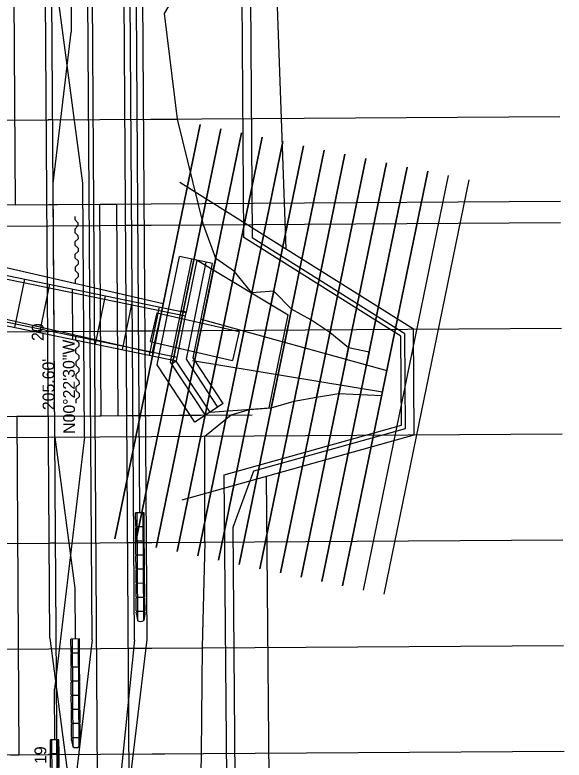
# Model space of a CAD drawing. Extents: x 2283072 to 2287933, y 586198 to 587702.
# Drawn here: x 2284424.4 to 2284554.3, y 587086.3 to 587262.4 of the extents above; entities that cross this region are included whole.
import ezdxf

# ---------------------------------------------------------------- set-up
doc = ezdxf.new("R2010")
doc.units = 0
for name, color, linetype in [('_CIVIL_CONSTRUCTION', 7, 'Continuous'), ('DR_X_Ditch', 7, 'Continuous'), ('DR_X_Headwall', 7, 'Continuous'), ('DT_X_Contour_Major', 7, 'Continuous'), ('DT_X_Island', 7, 'Continuous'), ('DT_X_Terrain_Boundary', 7, 'Continuous'), ('DT_X_Void', 7, 'Continuous'), ('HY_X_Water_Edge', 7, 'Continuous'), ('PV_X_Driveway', 7, 'Continuous'), ('PV_X_Shoulder_Aggregate', 7, 'Continuous'), ('RD_P_Fence', 7, 'Continuous'), ('RD_X_Cells', 7, 'Continuous'), ('RD_X_Fence', 7, 'Continuous'), ('RD_X_Gate', 7, 'Continuous'), ('RS_Raster1', 7, 'Continuous'), ('RW_P_Esmt_SH', 7, 'Continuous'), ('RW_P_Esmt_TMP', 7, 'Continuous'), ('SV_P_Control_Cells_Set', 7, 'Continuous'), ('SV_P_Mon_Cells_Set', 7, 'Continuous'), ('SV_X_Control_Cells_Found', 7, 'Continuous'), ('SV_X_Random_Point', 7, 'Continuous'), ('SV_X_Toe_of_Slope', 7, 'Continuous')]:
    doc.layers.add(name, color=color, linetype=linetype)

msp = doc.modelspace()

# ---------------------------------------------------------------- linework, layer by layer
at = {"layer": '_CIVIL_CONSTRUCTION'}
for p, q in [((2284440.46, 587222.64), (2284432.57, 587282.12)), ((2284442.67, 587114.69), (2284441.59, 587278.56)), ((2284452.67, 587114.75), (2284451.59, 587278.62)), ((2284453.97, 587144.73), (2284453.18, 587264.73)), ((2284440.85, 587162.64), (2284440.46, 587222.64)), ((2284440.85, 587162.64), (2284433.74, 587103.07)), ((2284454.97, 587144.74), (2284452.97, 587144.72)), ((2284452.99, 587141.56), (2284452.97, 587144.72)), ((2284453.47, 587119.24), (2284453.3, 587144.72)), ((2284454.64, 587144.73), (2284454.8, 587119.25)), ((2284454.99, 587141.57), (2284454.97, 587144.74)), ((2284452.99, 587141.56), (2284453.16, 587141.39)), ((2284453.16, 587141.39), (2284452.99, 587141.22)), ((2284453.01, 587138.22), (2284452.99, 587141.22)), ((2284454.83, 587141.4), (2284453.16, 587141.39)), ((2284454.99, 587141.57), (2284454.83, 587141.4)), ((2284454.83, 587141.4), (2284454.99, 587141.24)), ((2284455.01, 587138.24), (2284454.99, 587141.24)), ((2284453.01, 587138.22), (2284453.18, 587138.06)), ((2284455.01, 587138.24), (2284454.85, 587138.07)), ((2284453.18, 587138.06), (2284453.02, 587137.89)), ((2284453.03, 587134.89), (2284453.02, 587137.89)), ((2284454.85, 587138.07), (2284453.18, 587138.06)), ((2284454.85, 587138.07), (2284455.02, 587137.9)), ((2284455.03, 587134.9), (2284455.02, 587137.9)), ((2284453.03, 587134.89), (2284453.2, 587134.72)), ((2284453.2, 587134.72), (2284453.04, 587134.56)), ((2284454.87, 587134.73), (2284453.2, 587134.72)), ((2284455.03, 587134.9), (2284454.87, 587134.73)), ((2284454.87, 587134.73), (2284455.04, 587134.57)), ((2284453.06, 587131.56), (2284453.04, 587134.56)), ((2284455.06, 587131.57), (2284455.04, 587134.57)), ((2284453.06, 587131.56), (2284453.22, 587131.39)), ((2284453.22, 587131.39), (2284453.06, 587131.22)), ((2284453.08, 587128.22), (2284453.06, 587131.22)), ((2284454.89, 587131.4), (2284453.22, 587131.39)), ((2284455.06, 587131.57), (2284454.89, 587131.4)), ((2284454.89, 587131.4), (2284455.06, 587131.24)), ((2284455.08, 587128.24), (2284455.06, 587131.24)), ((2284453.08, 587128.22), (2284453.25, 587128.06)), ((2284453.25, 587128.06), (2284453.08, 587127.89)), ((2284453.1, 587124.89), (2284453.08, 587127.89)), ((2284454.91, 587128.07), (2284453.25, 587128.06)), ((2284455.08, 587128.24), (2284454.91, 587128.07)), ((2284454.91, 587128.07), (2284455.08, 587127.9)), ((2284455.08, 587127.9), (2284455.1, 587124.9)), ((2284453.1, 587124.89), (2284453.27, 587124.72)), ((2284453.27, 587124.72), (2284453.1, 587124.56)), ((2284453.12, 587121.56), (2284453.1, 587124.56)), ((2284454.93, 587124.74), (2284453.27, 587124.72)), ((2284455.1, 587124.9), (2284454.93, 587124.74)), ((2284454.93, 587124.74), (2284455.1, 587124.57)), ((2284455.1, 587124.57), (2284455.12, 587121.57)), ((2284453.12, 587121.56), (2284453.29, 587121.39)), ((2284453.29, 587121.39), (2284453.12, 587121.22)), ((2284453.13, 587120.79), (2284453.12, 587121.22)), ((2284453.13, 587120.79), (2284453.39, 587119.29)), ((2284454.96, 587121.4), (2284453.29, 587121.39)), ((2284455.13, 587120.8), (2284454.89, 587119.3)), ((2284455.12, 587121.57), (2284454.96, 587121.4)), ((2284454.96, 587121.4), (2284455.12, 587121.24)), ((2284455.12, 587121.24), (2284455.13, 587120.8)), ((2284442.67, 587114.69), (2284426.32, 586977.76)), ((2284452.67, 587114.75), (2284444.91, 587037.77)), ((2284433.82, 587091.07), (2284433.74, 587103.07)), ((2284434.82, 587091.07), (2284432.82, 587091.06)), ((2284432.84, 587087.89), (2284432.82, 587091.06)), ((2284433.32, 587065.57), (2284433.15, 587091.06)), ((2284434.49, 587091.07), (2284434.65, 587065.58)), ((2284434.84, 587087.91), (2284434.82, 587091.07)), ((2284432.84, 587087.89), (2284433.01, 587087.73)), ((2284433.01, 587087.73), (2284432.84, 587087.56)), ((2284432.86, 587084.56), (2284432.84, 587087.56)), ((2284434.68, 587087.74), (2284433.01, 587087.73)), ((2284434.84, 587087.91), (2284434.68, 587087.74)), ((2284434.68, 587087.74), (2284434.84, 587087.57)), ((2284434.86, 587084.57), (2284434.84, 587087.57))]:
    msp.add_line(p, q, dxfattribs=at)
msp.add_arc((2284454.13, 587120.4), 1.34, 236.1994, 304.5508, dxfattribs=at)
at = {"layer": 'DR_X_Ditch'}
for p, q in [((2284432.66, 587115.11), (2284431.63, 587272.79)), ((2284437.65, 587270.34), (2284437.73, 587258.34)), ((2284433.46, 587222.6), (2284437.73, 587258.34)), ((2284433.85, 587162.6), (2284433.46, 587222.6)), ((2284433.85, 587162.6), (2284438.59, 587126.91)), ((2284438.59, 587126.91), (2284438.67, 587114.91)), ((2284432.66, 587115.11), (2284445.17, 587020.81)), ((2284439.67, 587114.92), (2284437.67, 587114.9)), ((2284437.69, 587111.74), (2284437.67, 587114.9)), ((2284438.17, 587089.42), (2284438, 587114.91)), ((2284439.33, 587114.91), (2284439.5, 587089.43)), ((2284439.69, 587111.75), (2284439.67, 587114.92)), ((2284437.69, 587111.74), (2284437.85, 587111.57)), ((2284437.85, 587111.57), (2284437.69, 587111.4)), ((2284437.71, 587108.4), (2284437.69, 587111.4)), ((2284439.52, 587111.58), (2284437.85, 587111.57)), ((2284439.69, 587111.75), (2284439.52, 587111.58)), ((2284439.52, 587111.58), (2284439.69, 587111.42)), ((2284439.71, 587108.42), (2284439.69, 587111.42)), ((2284437.71, 587108.4), (2284437.88, 587108.24)), ((2284439.71, 587108.42), (2284439.54, 587108.25)), ((2284437.88, 587108.24), (2284437.71, 587108.07)), ((2284437.73, 587105.07), (2284437.71, 587108.07)), ((2284439.54, 587108.25), (2284437.88, 587108.24)), ((2284439.54, 587108.25), (2284439.71, 587108.08)), ((2284439.73, 587105.08), (2284439.71, 587108.08)), ((2284437.73, 587105.07), (2284437.9, 587104.91)), ((2284437.9, 587104.91), (2284437.73, 587104.74)), ((2284439.56, 587104.92), (2284437.9, 587104.91)), ((2284439.73, 587105.08), (2284439.56, 587104.92)), ((2284439.56, 587104.92), (2284439.73, 587104.75)), ((2284439.75, 587101.75), (2284439.73, 587104.75)), ((2284437.75, 587101.74), (2284437.73, 587104.74)), ((2284437.75, 587101.74), (2284437.92, 587101.57)), ((2284437.92, 587101.57), (2284437.75, 587101.4)), ((2284437.77, 587098.4), (2284437.75, 587101.4)), ((2284439.59, 587101.58), (2284437.92, 587101.57)), ((2284439.75, 587101.75), (2284439.59, 587101.58)), ((2284439.59, 587101.58), (2284439.75, 587101.42)), ((2284439.77, 587098.42), (2284439.75, 587101.42)), ((2284437.77, 587098.4), (2284437.94, 587098.24)), ((2284437.94, 587098.24), (2284437.78, 587098.07)), ((2284437.8, 587095.07), (2284437.78, 587098.07)), ((2284439.61, 587098.25), (2284437.94, 587098.24)), ((2284439.77, 587098.42), (2284439.61, 587098.25)), ((2284439.61, 587098.25), (2284439.78, 587098.08)), ((2284439.78, 587098.08), (2284439.8, 587095.08)), ((2284437.8, 587095.07), (2284437.96, 587094.91)), ((2284437.96, 587094.91), (2284437.8, 587094.74)), ((2284437.82, 587091.74), (2284437.8, 587094.74)), ((2284439.63, 587094.92), (2284437.96, 587094.91)), ((2284439.8, 587095.08), (2284439.63, 587094.92)), ((2284439.63, 587094.92), (2284439.8, 587094.75)), ((2284439.8, 587094.75), (2284439.82, 587091.75)), ((2284437.82, 587091.74), (2284437.98, 587091.57)), ((2284437.98, 587091.57), (2284437.82, 587091.4)), ((2284437.82, 587090.97), (2284437.82, 587091.4)), ((2284437.82, 587090.97), (2284438.08, 587089.47)), ((2284439.65, 587091.58), (2284437.98, 587091.57)), ((2284439.82, 587090.98), (2284439.58, 587089.48)), ((2284439.82, 587091.75), (2284439.65, 587091.58)), ((2284439.65, 587091.58), (2284439.82, 587091.42)), ((2284439.82, 587091.42), (2284439.82, 587090.98))]:
    msp.add_line(p, q, dxfattribs=at)
msp.add_arc((2284438.82, 587090.58), 1.34, 236.1994, 304.5508, dxfattribs=at)
at = {"layer": 'DR_X_Headwall'}
for p, q in [((2284480.09, 587278.8), (2284480.55, 587209.72)), ((2284516.69, 587187.04), (2284480.55, 587209.72)), ((2284516.84, 587164.67), (2284516.69, 587187.04)), ((2284480.95, 587154.63), (2284516.84, 587164.67)), ((2284476.02, 587141.37), (2284480.95, 587154.63)), ((2284476.87, 587042.07), (2284476.02, 587141.37))]:
    msp.add_line(p, q, dxfattribs=at)
at = {"layer": 'DT_X_Contour_Major'}
for p, q in [((2284458.07, 587179.74), (2284463.32, 587205.3)), ((2284471.16, 587203.68), (2284463.32, 587205.3)), ((2284403.08, 587203.99), (2284464.78, 587191.3)), ((2284403.24, 587204.81), (2284464.95, 587192.11)), ((2284463.74, 587192.45), (2284466.26, 587204.69)), ((2284464.97, 587192.2), (2284467.49, 587204.44)), ((2284464.98, 587181.07), (2284469.69, 587203.99)), ((2284466.57, 587181.37), (2284471.16, 587203.68)), ((2284424.4, 587188.55), (2284426.75, 587199.97)), ((2284430.28, 587187.34), (2284432.63, 587198.76)), ((2284438.11, 587185.72), (2284438.02, 587197.66)), ((2284443.5, 587184.62), (2284445.85, 587196.04)), ((2284449.87, 587183.31), (2284452.22, 587194.73)), ((2284400.89, 587193.38), (2284462.6, 587180.69)), ((2284401.06, 587194.2), (2284462.77, 587181.5)), ((2284456.23, 587182), (2284458.58, 587193.42)), ((2284461.25, 587180.35), (2284463.74, 587192.45)), ((2284462.6, 587180.69), (2284464.95, 587192.11)), ((2284462.6, 587180.69), (2284464.95, 587192.11)), ((2284462.6, 587180.69), (2284464.95, 587192.11)), ((2284464.97, 587192.2), (2284463.74, 587192.45)), ((2284464.95, 587192.11), (2284464.97, 587192.2)), ((2284462.58, 587180.61), (2284461.36, 587180.86)), ((2284462.58, 587180.61), (2284461.54, 587179.92)), ((2284462.58, 587180.61), (2284462.6, 587180.69)), ((2284470.56, 587168.5), (2284462.58, 587180.61)), ((2284472.44, 587169.73), (2284464.98, 587181.07)), ((2284473.69, 587170.56), (2284466.57, 587181.37)), ((2284467.01, 587166.16), (2284458.07, 587179.74)), ((2284469.52, 587167.81), (2284461.25, 587180.35)), ((2284473.69, 587170.56), (2284467.01, 587166.16))]:
    msp.add_line(p, q, dxfattribs=at)
at = {"layer": 'DT_X_Island'}
for p, q in [((2284424.09, 587278.43), (2284424.49, 587217.54)), ((2284424.49, 587217.54), (2284444.49, 587217.67)), ((2284444.82, 587167.67), (2284444.49, 587217.67)), ((2284424.82, 587167.54), (2284444.82, 587167.67)), ((2284424.82, 587167.54), (2284425.34, 587087.54)), ((2284423.34, 587087.53), (2284425.34, 587087.54))]:
    msp.add_line(p, q, dxfattribs=at)
at = {"layer": 'DT_X_Terrain_Boundary'}
for p, q in [((2284455.67, 587114.77), (2284454.48, 587295.32)), ((2284442.59, 587278.55), (2284443.94, 587072.96)), ((2284446.36, 587037.79), (2284455.67, 587114.77))]:
    msp.add_line(p, q, dxfattribs=at)
at = {"layer": 'DT_X_Void'}
for p, q in [((2284313.36, 587236.81), (2284553.36, 587238.38)), ((2284468.22, 587236.53), (2284448.07, 587138.59)), ((2284473.12, 587235.53), (2284452.97, 587137.58)), ((2284478.01, 587234.52), (2284457.86, 587136.57)), ((2284482.91, 587233.51), (2284462.76, 587135.56)), ((2284487.81, 587232.5), (2284467.66, 587134.56)), ((2284492.71, 587231.5), (2284472.56, 587133.55)), ((2284497.6, 587230.49), (2284477.45, 587132.54)), ((2284502.5, 587229.48), (2284482.35, 587131.53)), ((2284507.4, 587228.47), (2284487.25, 587130.52)), ((2284512.3, 587227.47), (2284492.15, 587129.52)), ((2284517.19, 587226.46), (2284497.04, 587128.51)), ((2284522.09, 587225.45), (2284501.94, 587127.5)), ((2284313.5, 587216.81), (2284553.49, 587218.38)), ((2284313.53, 587211.81), (2284553.52, 587213.38)), ((2284313.3, 587186.81), (2284553.69, 587188.38)), ((2284313.82, 587166.81), (2284480.56, 587167.9)), ((2284388.59, 587162.3), (2284553.85, 587163.38)), ((2284314.02, 587136.81), (2284554.01, 587138.38)), ((2284314.18, 587111.81), (2284554.18, 587113.38)), ((2284314.35, 587086.81), (2284554.34, 587088.38))]:
    msp.add_line(p, q, dxfattribs=at)
at = {"layer": 'HY_X_Water_Edge'}
for p, q in [((2284448.07, 587138.59), (2284468.22, 587236.53)), ((2284452.97, 587137.58), (2284473.12, 587235.53)), ((2284457.86, 587136.57), (2284478.01, 587234.52)), ((2284462.76, 587135.56), (2284482.91, 587233.51)), ((2284467.66, 587134.56), (2284487.81, 587232.5)), ((2284472.56, 587133.55), (2284492.71, 587231.5)), ((2284477.45, 587132.54), (2284497.6, 587230.49)), ((2284482.35, 587131.53), (2284502.5, 587229.48)), ((2284487.25, 587130.52), (2284507.4, 587228.47)), ((2284492.15, 587129.52), (2284512.3, 587227.47)), ((2284497.04, 587128.51), (2284517.19, 587226.46)), ((2284501.94, 587127.5), (2284522.09, 587225.45)), ((2284506.84, 587126.49), (2284526.99, 587224.44)), ((2284511.74, 587125.49), (2284531.89, 587223.44))]:
    msp.add_line(p, q, dxfattribs=at)
at = {"layer": 'PV_X_Driveway'}
for p, q in [((2284457.98, 587192.03), (2284456.42, 587185.21)), ((2284457.98, 587192.03), (2284477.48, 587187.58)), ((2284477.48, 587187.58), (2284475.92, 587180.76)), ((2284456.42, 587185.21), (2284475.92, 587180.76))]:
    msp.add_line(p, q, dxfattribs=at)
at = {"layer": 'RD_P_Fence'}
for p, q in [((2284478.54, 587209.79), (2284478.09, 587278.78)), ((2284515.7, 587186.49), (2284478.54, 587209.79)), ((2284515.84, 587165.43), (2284515.7, 587186.49)), ((2284473.91, 587153.7), (2284515.84, 587165.43)), ((2284474.86, 587043.23), (2284473.91, 587153.7))]:
    msp.add_line(p, q, dxfattribs=at)
at = {"layer": 'RD_X_Cells'}
for p, q in [((2284438.54, 587214.78), (2284438.55, 587214.03)), ((2284438.55, 587214.03), (2284439.3, 587213.28)), ((2284439.31, 587212.53), (2284438.56, 587211.78)), ((2284439.3, 587213.28), (2284439.31, 587212.53)), ((2284438.56, 587211.78), (2284438.57, 587211.03)), ((2284438.57, 587211.03), (2284439.32, 587210.28)), ((2284439.33, 587209.53), (2284438.58, 587208.78)), ((2284438.58, 587208.78), (2284438.59, 587208.03)), ((2284439.32, 587210.28), (2284439.33, 587209.53)), ((2284438.59, 587208.03), (2284439.34, 587207.28)), ((2284439.34, 587207.28), (2284439.35, 587206.53)), ((2284439.35, 587206.53), (2284438.6, 587205.78)), ((2284438.6, 587205.78), (2284438.61, 587205.03)), ((2284438.61, 587205.03), (2284439.36, 587204.28)), ((2284439.36, 587203.53), (2284438.62, 587202.78)), ((2284439.36, 587204.28), (2284439.36, 587203.53)), ((2284438.62, 587202.78), (2284438.62, 587202.03)), ((2284438.62, 587202.03), (2284439.38, 587201.28)), ((2284439.38, 587200.53), (2284438.64, 587199.78)), ((2284439.38, 587201.28), (2284439.38, 587200.53)), ((2284438.64, 587199.78), (2284438.64, 587199.03)), ((2284438.75, 587186.41), (2284438.75, 587185.66)), ((2284438.75, 587185.66), (2284439.51, 587184.91)), ((2284439.51, 587184.16), (2284438.76, 587183.41)), ((2284439.51, 587184.91), (2284439.51, 587184.16)), ((2284438.76, 587183.41), (2284438.77, 587182.66)), ((2284438.77, 587182.66), (2284439.52, 587181.91)), ((2284439.53, 587181.16), (2284438.78, 587180.41)), ((2284439.52, 587181.91), (2284439.53, 587181.16)), ((2284438.78, 587180.41), (2284438.79, 587179.66)), ((2284438.79, 587179.66), (2284439.54, 587178.91)), ((2284439.54, 587178.91), (2284439.55, 587178.16)), ((2284439.55, 587178.16), (2284438.8, 587177.41)), ((2284438.8, 587177.41), (2284438.81, 587176.66)), ((2284438.81, 587176.66), (2284439.56, 587175.91)), ((2284439.56, 587175.91), (2284439.57, 587175.16)), ((2284439.57, 587175.16), (2284438.82, 587174.41)), ((2284438.82, 587174.41), (2284438.83, 587173.66)), ((2284438.83, 587173.66), (2284439.58, 587172.91)), ((2284439.59, 587172.16), (2284438.84, 587171.41)), ((2284439.58, 587172.91), (2284439.59, 587172.16)), ((2284438.84, 587171.41), (2284438.85, 587170.66))]:
    msp.add_line(p, q, dxfattribs=at)
at = {"layer": 'RD_X_Fence'}
for p, q in [((2284467.49, 587204.44), (2284489.08, 587191.55)), ((2284484.55, 587169.54), (2284489.08, 587191.55)), ((2284470.56, 587168.5), (2284484.55, 587169.54))]:
    msp.add_line(p, q, dxfattribs=at)
at = {"layer": 'RD_X_Gate'}
for p, q in [((2284468.46, 587190.54), (2284512.4, 587178.34)), ((2284466.44, 587180.75), (2284511.37, 587173.36))]:
    msp.add_line(p, q, dxfattribs=at)
at = {"layer": 'RS_Raster1'}
for p, q in [((2284433.36, 587237.6), (2284432.16, 587237.59)), ((2284433.69, 587187.6), (2284431.69, 587187.58)), ((2284434.02, 587137.6), (2284432.82, 587137.59)), ((2284434.34, 587087.6), (2284432.34, 587087.59))]:
    msp.add_line(p, q, dxfattribs=at)
at = {"layer": 'RW_P_Esmt_SH'}
for p, q in [((2284518.69, 587188.15), (2284463.46, 587222.79)), ((2284518.85, 587163.15), (2284518.69, 587188.15)), ((2284463.95, 587147.79), (2284518.85, 587163.15))]:
    msp.add_line(p, q, dxfattribs=at)
at = {"layer": 'RW_P_Esmt_TMP'}
for p, q in [((2284488.56, 587207.05), (2284483.76, 587344.32)), ((2284484.94, 587033.53), (2284483.91, 587153.38))]:
    msp.add_line(p, q, dxfattribs=at)
at = {"layer": 'SV_P_Control_Cells_Set'}
for p, q in [((2284411.05, 587205.27), (2284459.49, 587194.21)), ((2284408.4, 587193.65), (2284456.84, 587182.59)), ((2284459.49, 587194.21), (2284456.84, 587182.59))]:
    msp.add_line(p, q, dxfattribs=at)
at = {"layer": 'SV_X_Control_Cells_Found'}
for p, q in [((2284444.49, 587217.67), (2284448.49, 587217.69)), ((2284448.82, 587167.7), (2284448.49, 587217.69)), ((2284444.82, 587167.67), (2284448.82, 587167.7))]:
    msp.add_line(p, q, dxfattribs=at)
at = {"layer": 'SV_X_Random_Point'}
msp.add_line((2284434.44, 587072.89), (2284433.09, 587278.49), dxfattribs=at)
msp.add_line((2284434.44, 587072.89), (2284433.09, 587278.49), dxfattribs=at)
at = {"layer": 'SV_X_Toe_of_Slope'}
for p, q in [((2284450.09, 587278.6), (2284451.5, 587063.67)), ((2284450.36, 587237.71), (2284462.89, 587237.79)), ((2284468.99, 587212.83), (2284462.89, 587237.79)), ((2284450.53, 587212.71), (2284468.99, 587212.83)), ((2284471.91, 587204.83), (2284468.92, 587190.31)), ((2284476.38, 587201.76), (2284473.75, 587188.98)), ((2284480.44, 587196.7), (2284478.58, 587187.65)), ((2284485.63, 587197.11), (2284483.41, 587186.32)), ((2284489.86, 587192.85), (2284488.24, 587184.99)), ((2284494.44, 587190.31), (2284493.07, 587183.66)), ((2284450.69, 587187.71), (2284462.78, 587187.79)), ((2284498.95, 587187.39), (2284497.91, 587182.33)), ((2284503.3, 587183.73), (2284502.74, 587181)), ((2284508.2, 587182.74), (2284507.57, 587179.67)), ((2284465.59, 587174.12), (2284466.95, 587180.72)), ((2284469.4, 587167.83), (2284471.88, 587179.9)), ((2284474.51, 587167.86), (2284476.82, 587179.09)), ((2284479.89, 587169.19), (2284481.76, 587178.27)), ((2284485.06, 587169.51), (2284486.69, 587177.45)), ((2284490.49, 587171.1), (2284491.63, 587176.63)), ((2284495.79, 587172.06), (2284496.57, 587175.81)), ((2284501.08, 587172.93), (2284501.5, 587175)), ((2284506.13, 587172.7), (2284506.44, 587174.18)), ((2284450.82, 587167.71), (2284475.56, 587167.87)), ((2284469.36, 587137.83), (2284469.33, 587162.83)), ((2284451.02, 587137.71), (2284469.36, 587137.83)), ((2284451.18, 587112.71), (2284468.69, 587112.82)), ((2284451.34, 587087.71), (2284468.5, 587087.82))]:
    msp.add_line(p, q, dxfattribs=at)
for points in [[(2284462.89, 587237.79), (2284459.81, 587262.77), (2284459.81, 587262.77), (2284474.94, 587288.64), (2284469.52, 587315.41), (2284448.81, 587339.91)], [(2284508.2, 587182.74), (2284503.3, 587183.73), (2284498.95, 587187.39), (2284494.44, 587190.31), (2284489.86, 587192.85), (2284485.63, 587197.11), (2284480.44, 587196.7), (2284476.38, 587201.76), (2284471.91, 587204.83), (2284468.99, 587212.83)], [(2284469.33, 587162.83), (2284475.56, 587167.87), (2284479.89, 587169.19), (2284485.06, 587169.51), (2284490.49, 587171.1), (2284495.79, 587172.06), (2284501.08, 587172.93), (2284511.19, 587172.48)], [(2284469.36, 587137.83), (2284468.69, 587112.94), (2284468.5, 587087.92), (2284468.08, 587063.79), (2284459.9, 587038.03)]]:
    msp.add_lwpolyline(points, dxfattribs=at)
msp.add_lwpolyline([(2284466.38, 587221.43), (2284466.38, 587221.43), (2284466.38, 587221.43)], close=True, dxfattribs=at)

# ---------------------------------------------------------------- texts
at = {"layer": 'PV_X_Shoulder_Aggregate'}
msp.add_text('N00°22\'30"W', height=2.8, rotation=90.3751, dxfattribs=at).set_placement((2284438.65, 587163.41))
at = {"layer": 'RS_Raster1'}
for s, p in [('20', (2284431.2, 587185.35)), ('19', (2284431.86, 587085.38))]:
    msp.add_text(s, height=2.8, rotation=90.3751, dxfattribs=at).set_placement(p)
at = {"layer": 'SV_P_Mon_Cells_Set'}
msp.add_text("205.60'", height=2.8, rotation=90.3751, dxfattribs=at).set_placement((2284433.77, 587169.01))

doc.saveas('drawing.dxf')
